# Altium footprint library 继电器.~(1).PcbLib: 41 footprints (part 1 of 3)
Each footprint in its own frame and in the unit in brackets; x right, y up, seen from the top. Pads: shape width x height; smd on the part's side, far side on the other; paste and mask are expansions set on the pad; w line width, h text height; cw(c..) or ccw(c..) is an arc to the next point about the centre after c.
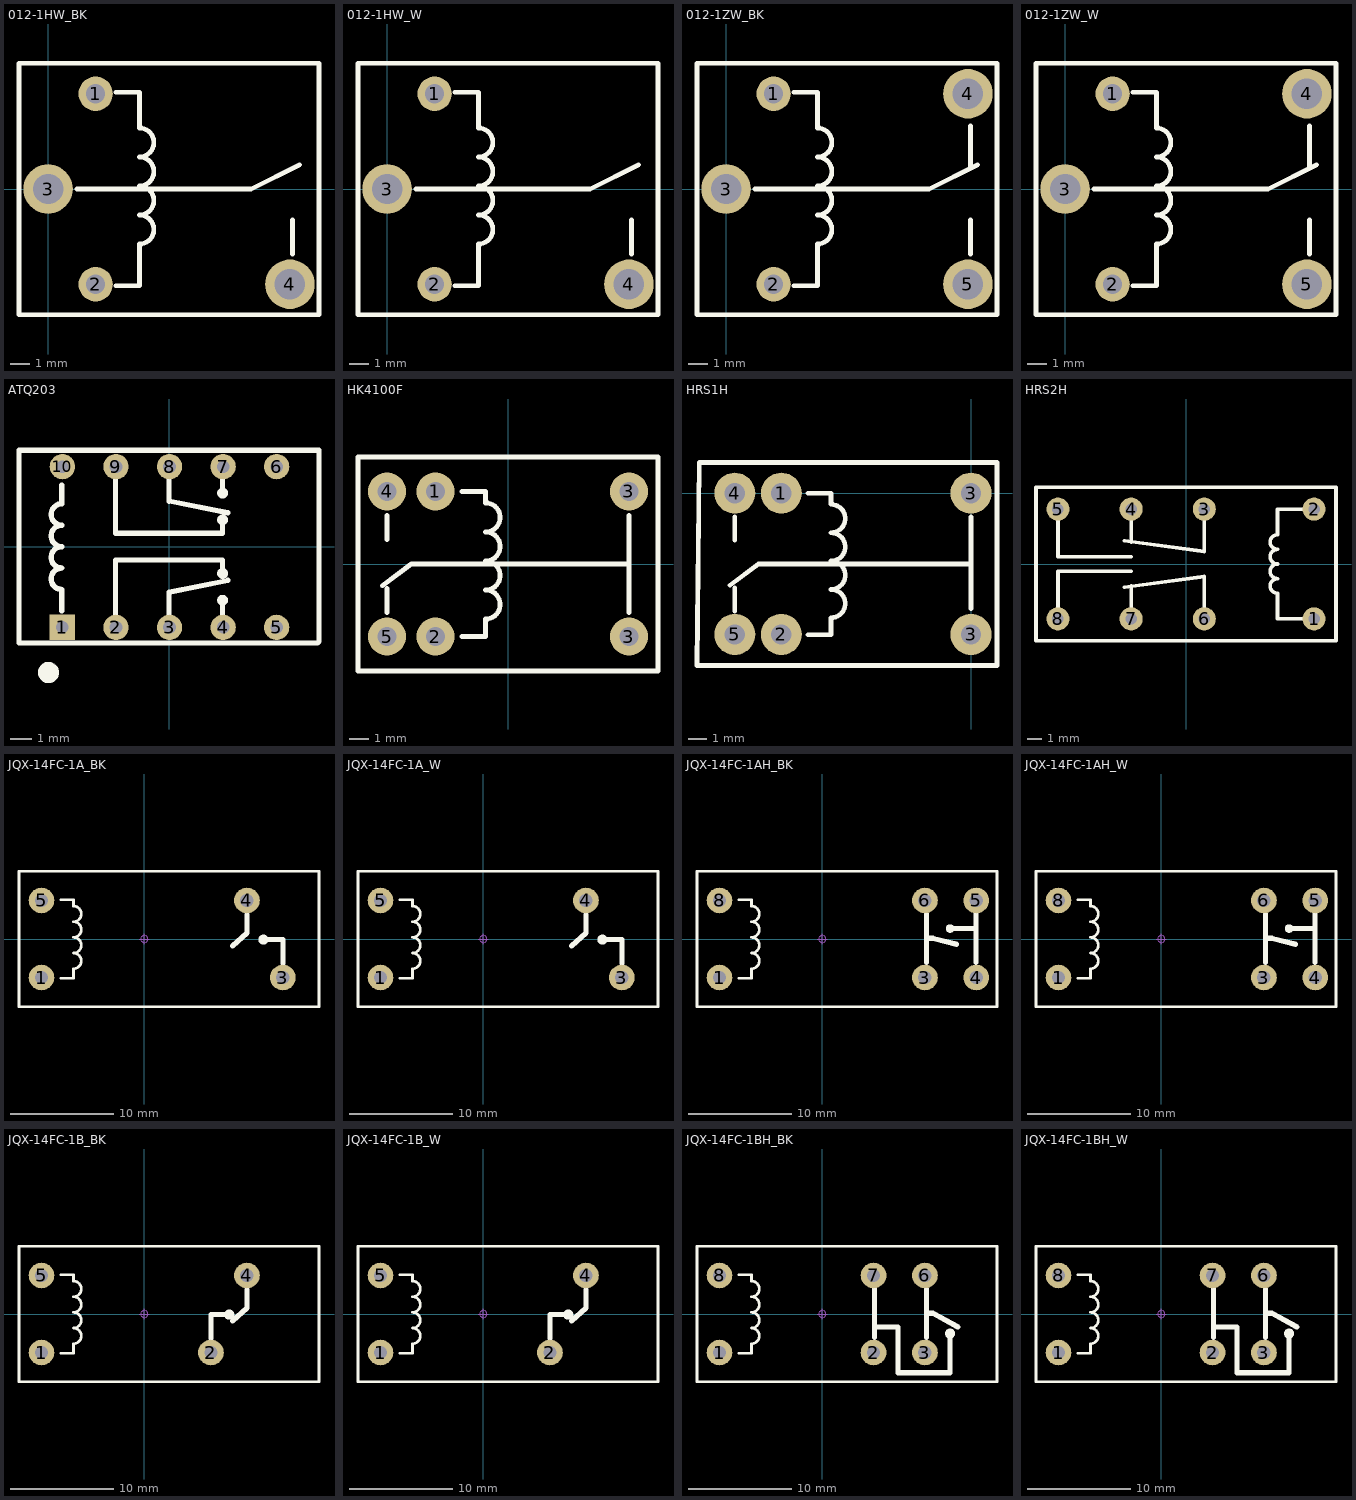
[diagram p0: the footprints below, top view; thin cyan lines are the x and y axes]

## 012-1HW_BK [mm] "单刀单投/常开"
pads (4):
  round 1.8 hole 1: 1(2.5,5) 2(2.5,-5)
  round 2.6 hole 1.6: 3(0,0) 4(12.7,-5)
Top Overlay:
  lines w0.254: 1.524,0 10.668,0 13.208,1.27 ; 3.556,-5.08 4.794,-5.08 4.794,-2.89 ccw(c4.794,-2.128) 4.794,-1.366 ccw(c4.794,-0.604) 4.794,0.158 ccw(c4.794,0.92) 4.794,1.682 ccw(c4.794,2.444) 4.794,3.206 4.794,5.08 3.556,5.08 ; 12.827,-3.429 12.838,-1.62 ; -1.524,-6.604 -1.524,6.604 14.224,6.604 14.224,-6.604 -1.524,-6.604
3D body: height 12.9, standoff -3.6, extent -1.5,-6.1 14,6.1

## 012-1HW_W [mm] "单刀单投/常开"
pads (4):
  round 1.8 hole 1: 1(2.5,5) 2(2.5,-5)
  round 2.6 hole 1.6: 3(0,0) 4(12.7,-5)
Top Overlay:
  lines w0.254: 1.524,0 10.668,0 13.208,1.27 ; 3.556,-5.08 4.794,-5.08 4.794,-2.89 ccw(c4.794,-2.128) 4.794,-1.366 ccw(c4.794,-0.604) 4.794,0.158 ccw(c4.794,0.92) 4.794,1.682 ccw(c4.794,2.444) 4.794,3.206 4.794,5.08 3.556,5.08 ; 12.827,-3.429 12.838,-1.62 ; -1.524,-6.604 14.224,-6.604 14.224,6.604 -1.524,6.604 -1.524,-6.604
3D body: height 12.9, standoff -3.6, extent -1.5,-6.1 14,6.1

## 012-1ZW_BK [mm] "单刀双投"
pads (5):
  round 1.8 hole 1: 1(2.5,5) 2(2.5,-5)
  round 2.6 hole 1.6: 3(0,0) 4(12.7,5) 5(12.7,-5)
Top Overlay:
  lines w0.254: 1.524,0 10.668,0 13.208,1.27 ; 3.556,-5.08 4.794,-5.08 4.794,-2.89 ccw(c4.794,-2.128) 4.794,-1.366 ccw(c4.794,-0.604) 4.794,0.158 ccw(c4.794,0.92) 4.794,1.682 ccw(c4.794,2.444) 4.794,3.206 4.794,5.08 3.556,5.08 ; 12.827,-3.429 12.838,-1.62 ; 12.838,1.174 12.838,3.302 ; -1.524,-6.604 14.224,-6.604 14.224,6.604 -1.524,6.604 -1.524,-6.604
3D body: height 12.9, standoff -3.6, extent -1.5,-6.1 14,6.1

## 012-1ZW_W [mm] "单刀双投"
pads (5):
  round 1.8 hole 1: 1(2.5,5) 2(2.5,-5)
  round 2.6 hole 1.6: 3(0,0) 4(12.7,5) 5(12.7,-5)
Top Overlay:
  lines w0.254: 1.524,0 10.668,0 13.208,1.27 ; 3.556,-5.08 4.794,-5.08 4.794,-2.89 ccw(c4.794,-2.128) 4.794,-1.366 ccw(c4.794,-0.604) 4.794,0.158 ccw(c4.794,0.92) 4.794,1.682 ccw(c4.794,2.444) 4.794,3.206 4.794,5.08 3.556,5.08 ; 12.827,-3.429 12.838,-1.62 ; 12.838,1.174 12.838,3.302 ; -1.524,-6.604 -1.524,6.604 14.224,6.604 14.224,-6.604 -1.524,-6.604
3D body: height 12.9, standoff -3.6, extent -1.5,-6.1 14,6.1

## ATQ203 [mm] "双刀双投"
pads (10):
  rect 1.2x1.2 hole 0.6: 1(-5.055,-3.829)
  round 1.2 hole 0.6: 2(-2.515,-3.829) 3(0.025,-3.829) 4(2.565,-3.829) 5(5.105,-3.829) 6(5.105,3.791) 7(2.565,3.791) 8(0.025,3.791) 9(-2.515,3.791) 10(-5.055,3.791)
Top Overlay:
  circle w0.254: c2.54,-2.54 r0.127
  circle w0.254: c2.54,-1.27 r0.127
  circle w0.254: c2.54,1.27 r0.127
  circle w0.254: c2.54,2.54 r0.127
  circle w0.5: c-5.715,-5.969 r0.25
  lines w0.254: -5.08,-3.048 -5.08,-2.032 cw(c-5.08,-1.524) -5.08,-1.016 cw(c-5.08,-0.508) -5.08,0 cw(c-5.08,0.508) -5.08,1.016 cw(c-5.08,1.524) -5.08,2.032 -5.08,2.921 ; -2.54,-3.175 -2.54,-2.159 -2.54,-0.635 2.54,-0.635 2.54,-1.27 ; -2.54,3.175 -2.54,2.159 -2.54,0.635 2.54,0.635 2.54,1.27 ; 0,-3.175 0,-2.159 2.784,-1.602 ; 0,3.175 0,2.159 2.784,1.602 ; 2.54,-3.175 2.54,-2.54 ; 2.54,2.54 2.54,3.175 ; -7.112,-4.572 7.04,-4.572 7.112,-4.5 7.112,4.572 -7.112,4.572 -7.112,-4.572
3D body: height 5.25, standoff -3.5, extent -7,-4.5 7,4.5

## HK4100F [mm] "单刀双投"
pads (6):
  round 2 hole 1: 1(-3.81,3.81) 2(-3.81,-3.81) 3(6.35,-3.81) 3(6.35,3.81) 4(-6.35,3.81) 5(-6.35,-3.81)
Top Overlay:
  lines w0.254: -6.604,-1.143 -5.08,0 6.35,0 ; -6.35,-2.54 -6.35,-1.27 ; -6.35,1.27 -6.35,2.54 ; -2.413,-3.81 -1.175,-3.81 -1.175,-2.89 ccw(c-1.175,-2.128) -1.175,-1.366 ccw(c-1.175,-0.604) -1.175,0.158 ccw(c-1.175,0.92) -1.175,1.682 ccw(c-1.175,2.444) -1.175,3.206 -1.175,3.81 -2.413,3.81 ; 6.35,-2.54 6.35,2.54 ; -7.874,-5.613 -7.874,5.613 7.874,5.613 7.874,-5.613 -7.874,-5.613
3D body: height 12.2, standoff -3.3, extent -7.75,-5.5 7.75,5.5

## HRS1H [mm] "单刀双投"
pads (6):
  round 2.2 hole 1.1: 1(-10.2,0) 2(-10.2,-7.6) 3(0,-7.6) 3(0,0) 4(-12.7,0) 5(-12.7,-7.6)
Top Overlay:
  lines w0.254: -12.954,-4.953 -11.43,-3.81 0,-3.81 ; -12.7,-6.35 -12.7,-5.08 ; -12.7,-2.54 -12.7,-1.27 ; -8.763,-7.62 -7.525,-7.62 -7.525,-6.7 ccw(c-7.525,-5.938) -7.525,-5.176 ccw(c-7.525,-4.414) -7.525,-3.652 ccw(c-7.525,-2.89) -7.525,-2.128 ccw(c-7.525,-1.366) -7.525,-0.604 -7.525,0 -8.763,0 ; 0,-6.223 0,-1.27 ; -14.732,-9.271 1.397,-9.271 1.397,1.651 -14.605,1.651 -14.732,-9.271
3D body: height 11.8, standoff -3.3, extent -14.4,-9.05 1.1,1.45

## HRS2H [mm] "双刀双投"
pads (8):
  round 1.6 hole 0.8: 1(8.89,-3.81) 2(8.89,3.81) 3(1.27,3.81) 4(-3.81,3.81) 5(-8.89,3.81) 6(1.27,-3.81) 7(-3.81,-3.81) 8(-8.89,-3.81)
Top Overlay:
  lines w0.254: -8.89,-3.81 -8.89,-0.508 -3.81,-0.508 ; -8.89,3.81 -8.89,0.508 -3.81,0.508 ; -4.27,-1.621 1.27,-0.866 1.27,-1.27 1.27,-3.81 ; -4.27,1.621 1.27,0.866 1.27,1.27 1.27,3.81 ; -3.81,-3.81 -3.81,-1.524 ; -3.81,1.524 -3.81,3.81 ; 8.89,-3.81 6.35,-3.81 6.35,-2.032 cw(c6.35,-1.524) 6.35,-1.016 cw(c6.35,-0.508) 6.35,0 cw(c6.35,0.508) 6.35,1.016 cw(c6.35,1.524) 6.35,2.032 6.35,3.81 8.89,3.81 ; -10.414,-5.334 10.414,-5.334 10.414,5.334 -10.414,5.334 -10.414,-5.334
3D body: height 10.91, standoff -4, extent -10.1,-4.95 10.1,4.95

## JQX-14FC-1A_BK [mm] "单刀常开，长：29mm，宽：13mm，高：26mm"
pads (4):
  round 2.5 hole 1.3: 1(-10,-3.75) 3(13.5,-3.75) 4(10,3.75) 5(-10,3.75)
Top Overlay:
  circle w0.254: c11.595,-0.06 r0.359
  lines w0.25: -12.192,-6.604 17.018,-6.604 17.018,6.604 -12.065,6.604 -12.192,6.604 -12.192,-6.604
  lines w0.254: -8.128,-3.81 -6.89,-3.81 -6.89,-2.89 ccw(c-6.89,-2.128) -6.89,-1.366 ccw(c-6.89,-0.604) -6.89,0.158 ccw(c-6.89,0.92) -6.89,1.682 ccw(c-6.89,2.444) -6.89,3.206 -6.89,3.81 -8.128,3.81
  lines w0.508: 8.603,-0.695 10,0.575 10,2.353 ; 11.595,-0.06 13.5,-0.06 13.5,-2.353
Mechanical 15:
  circle w0.05: c0,0 r0.35
  lines w0.05: -0.5,0 0.5,0 ; 0,-0.5 0,0.5
3D body: height 26.35, standoff -3.65, extent -12.1,-6.5 16.9,6.5

## JQX-14FC-1A_W [mm] "单刀常开，长：29mm，宽：13mm，高：26mm"
pads (4):
  round 2.5 hole 1.3: 1(-10,-3.75) 3(13.5,-3.75) 4(10,3.75) 5(-10,3.75)
Top Overlay:
  circle w0.254: c11.595,-0.06 r0.359
  lines w0.25: -12.192,-6.604 -12.192,6.604 -12.065,6.604 17.018,6.604 17.018,-6.604 -12.192,-6.604
  lines w0.254: -8.128,-3.81 -6.89,-3.81 -6.89,-2.89 ccw(c-6.89,-2.128) -6.89,-1.366 ccw(c-6.89,-0.604) -6.89,0.158 ccw(c-6.89,0.92) -6.89,1.682 ccw(c-6.89,2.444) -6.89,3.206 -6.89,3.81 -8.128,3.81
  lines w0.508: 8.603,-0.695 10,0.575 10,2.353 ; 11.595,-0.06 13.5,-0.06 13.5,-2.353
Mechanical 15:
  circle w0.05: c0,0 r0.35
  lines w0.05: -0.5,0 0.5,0 ; 0,-0.5 0,0.5
3D body: height 26.35, standoff -3.65, extent -12.1,-6.5 16.9,6.5

## JQX-14FC-1AH_BK [mm] "单刀常开，长：29mm，宽：13mm，高：26mm"
pads (6):
  round 2.5 hole 1.3: 1(-10,-3.75) 3(10,-3.75) 4(15,-3.75) 5(15,3.75) 6(10,3.75) 8(-10,3.75)
Top Overlay:
  circle w0.254: c12.446,1.016 r0.284
  lines w0.25: -12.192,-6.604 -12.192,6.604 -12.065,6.604 17.018,6.604 17.018,-6.604 -12.192,-6.604
  lines w0.254: -8.128,-3.81 -6.89,-3.81 -6.89,-2.89 ccw(c-6.89,-2.128) -6.89,-1.366 ccw(c-6.89,-0.604) -6.89,0.158 ccw(c-6.89,0.92) -6.89,1.682 ccw(c-6.89,2.444) -6.89,3.206 -6.89,3.81 -8.128,3.81
  lines w0.508: 10.16,-2.286 10.16,2.413 ; 10.16,0.064 10.795,0.064 13.081,-0.508 ; 12.446,1.016 14.986,1.016 ; 14.986,-2.286 14.986,2.413
Mechanical 15:
  circle w0.05: c0,0 r0.35
  lines w0.05: -0.5,0 0.5,0 ; 0,-0.5 0,0.5
3D body: height 26.35, standoff -3.65, extent -12.1,-6.5 16.9,6.5

## JQX-14FC-1AH_W [mm] "单刀常开，长：29mm，宽：13mm，高：26mm"
pads (6):
  round 2.5 hole 1.3: 1(-10,-3.75) 3(10,-3.75) 4(15,-3.75) 5(15,3.75) 6(10,3.75) 8(-10,3.75)
Top Overlay:
  circle w0.254: c12.446,1.016 r0.284
  lines w0.25: -12.192,-6.604 -12.192,6.604 -12.065,6.604 17.018,6.604 17.018,-6.604 -12.192,-6.604
  lines w0.254: -8.128,-3.81 -6.89,-3.81 -6.89,-2.89 ccw(c-6.89,-2.128) -6.89,-1.366 ccw(c-6.89,-0.604) -6.89,0.158 ccw(c-6.89,0.92) -6.89,1.682 ccw(c-6.89,2.444) -6.89,3.206 -6.89,3.81 -8.128,3.81
  lines w0.508: 10.16,-2.286 10.16,2.413 ; 10.16,0.064 10.795,0.064 13.081,-0.508 ; 12.446,1.016 14.986,1.016 ; 14.986,-2.286 14.986,2.413
Mechanical 15:
  circle w0.05: c0,0 r0.35
  lines w0.05: -0.5,0 0.5,0 ; 0,-0.5 0,0.5
3D body: height 26.35, standoff -3.65, extent -12.1,-6.5 16.9,6.5

## JQX-14FC-1B_BK [mm] "单刀常闭，长：29mm，宽：13mm，高：26mm"
pads (4):
  round 2.5 hole 1.3: 1(-10,-3.75) 2(6.5,-3.75) 4(10,3.75) 5(-10,3.75)
Top Overlay:
  circle w0.254: c8.278,-0.06 r0.37
  lines w0.25: -12.192,-6.604 -12.192,6.604 -12.065,6.604 17.018,6.604 17.018,-6.604 -12.192,-6.604
  lines w0.254: -8.128,-3.81 -6.89,-3.81 -6.89,-2.89 ccw(c-6.89,-2.128) -6.89,-1.366 ccw(c-6.89,-0.604) -6.89,0.158 ccw(c-6.89,0.92) -6.89,1.682 ccw(c-6.89,2.444) -6.89,3.206 -6.89,3.81 -8.128,3.81
  lines w0.508: 6.5,-2.353 6.5,-0.06 8.278,-0.06 ; 8.603,-0.695 10,0.575 10,2.353
Mechanical 15:
  circle w0.05: c0,0 r0.35
  lines w0.05: -0.5,0 0.5,0 ; 0,-0.5 0,0.5
3D body: height 26.35, standoff -3.65, extent -12.1,-6.5 16.9,6.5

## JQX-14FC-1B_W [mm] "单刀常闭，长：29mm，宽：13mm，高：26mm"
pads (4):
  round 2.5 hole 1.3: 1(-10,-3.75) 2(6.5,-3.75) 4(10,3.75) 5(-10,3.75)
Top Overlay:
  circle w0.254: c8.278,-0.06 r0.37
  lines w0.25: -12.192,-6.604 17.018,-6.604 17.018,6.604 -12.065,6.604 -12.192,6.604 -12.192,-6.604
  lines w0.254: -8.128,-3.81 -6.89,-3.81 -6.89,-2.89 ccw(c-6.89,-2.128) -6.89,-1.366 ccw(c-6.89,-0.604) -6.89,0.158 ccw(c-6.89,0.92) -6.89,1.682 ccw(c-6.89,2.444) -6.89,3.206 -6.89,3.81 -8.128,3.81
  lines w0.508: 6.5,-2.353 6.5,-0.06 8.278,-0.06 ; 8.603,-0.695 10,0.575 10,2.353
Mechanical 15:
  circle w0.05: c0,0 r0.35
  lines w0.05: -0.5,0 0.5,0 ; 0,-0.5 0,0.5
3D body: height 26.35, standoff -3.65, extent -12.1,-6.5 16.9,6.5

## JQX-14FC-1BH_BK [mm] "单刀常闭，长：29mm，宽：13mm，高：26mm"
pads (6):
  round 2.5 hole 1.3: 1(-10,-3.75) 2(5,-3.75) 3(10,-3.75) 6(10,3.75) 7(5,3.75) 8(-10,3.75)
Top Overlay:
  circle w0.254: c12.446,-1.905 r0.359
  lines w0.25: -12.192,-6.604 -12.192,6.604 -12.065,6.604 17.018,6.604 17.018,-6.604 -12.192,-6.604
  lines w0.254: -8.128,-3.81 -6.89,-3.81 -6.89,-2.89 ccw(c-6.89,-2.128) -6.89,-1.366 ccw(c-6.89,-0.604) -6.89,0.158 ccw(c-6.89,0.92) -6.89,1.682 ccw(c-6.89,2.444) -6.89,3.206 -6.89,3.81 -8.128,3.81
  lines w0.508: 5.08,-2.286 5.08,2.413 ; 5.08,-1.27 7.366,-1.27 7.366,-5.715 12.446,-5.715 12.446,-1.905 ; 10.16,-2.286 10.16,2.413 ; 10.16,0.064 10.795,0.064 13.208,-1.27
Mechanical 15:
  circle w0.05: c0,0 r0.35
  lines w0.05: -0.5,0 0.5,0 ; 0,-0.5 0,0.5
3D body: height 26.35, standoff -3.65, extent -12.1,-6.5 16.9,6.5

## JQX-14FC-1BH_W [mm] "单刀常闭，长：29mm，宽：13mm，高：26mm"
pads (6):
  round 2.5 hole 1.3: 1(-10,-3.75) 2(5,-3.75) 3(10,-3.75) 6(10,3.75) 7(5,3.75) 8(-10,3.75)
Top Overlay:
  circle w0.254: c12.446,-1.905 r0.359
  lines w0.25: -12.192,-6.604 -12.192,6.604 -12.065,6.604 17.018,6.604 17.018,-6.604 -12.192,-6.604
  lines w0.254: -8.128,-3.81 -6.89,-3.81 -6.89,-2.89 ccw(c-6.89,-2.128) -6.89,-1.366 ccw(c-6.89,-0.604) -6.89,0.158 ccw(c-6.89,0.92) -6.89,1.682 ccw(c-6.89,2.444) -6.89,3.206 -6.89,3.81 -8.128,3.81
  lines w0.508: 5.08,-2.286 5.08,2.413 ; 5.08,-1.27 7.366,-1.27 7.366,-5.715 12.446,-5.715 12.446,-1.905 ; 10.16,-2.286 10.16,2.413 ; 10.16,0.064 10.795,0.064 13.208,-1.27
Mechanical 15:
  circle w0.05: c0,0 r0.35
  lines w0.05: -0.5,0 0.5,0 ; 0,-0.5 0,0.5
3D body: height 26.35, standoff -3.65, extent -12.1,-6.5 16.9,6.5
